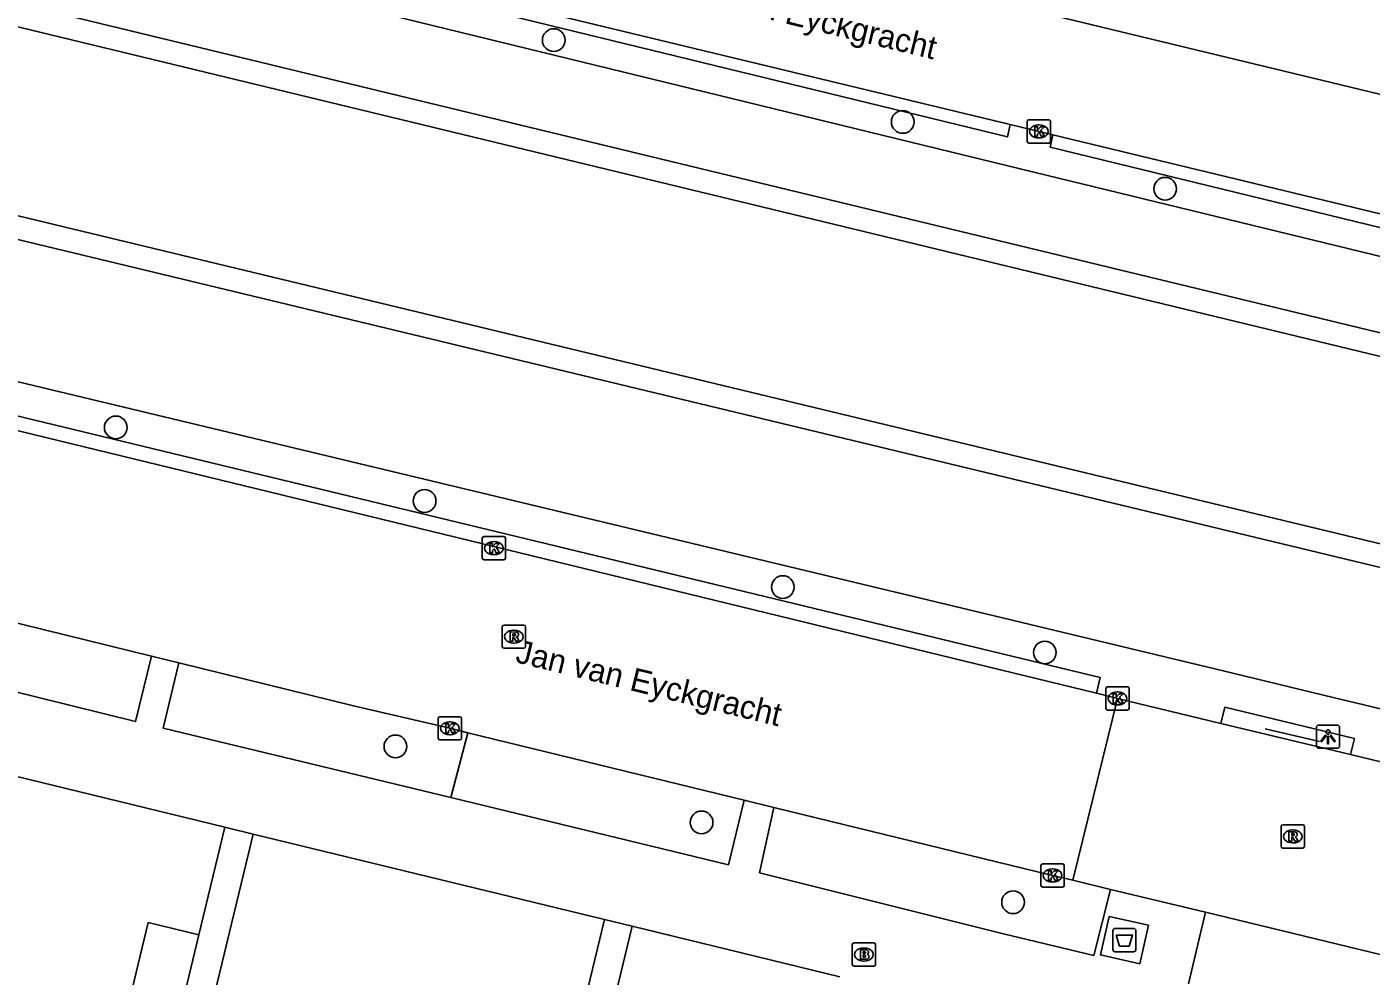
# Model space of a CAD drawing. Extents: x 162812 to 163818, y 381639 to 382470.
# Drawn here: x 163237.4 to 163295.2, y 382298.5 to 382339.3 of the extents above; entities that cross this region are included whole.
import ezdxf

# ---------------------------------------------------------------- set-up
doc = ezdxf.new("R2010")
doc.units = 0
for name, color, linetype in [('IMGEO_Afval_apart_plaats', 7, 'Continuous'), ('IMGEO_Boom', 7, 'Continuous'), ('IMGEO_Brandkraan', 7, 'Continuous'), ('IMGEO_Groenvoorziening', 7, 'Continuous'), ('IMGEO_Haag', 7, 'Continuous'), ('IMGEO_Hek', 7, 'Continuous'), ('IMGEO_Kolk', 7, 'Continuous'), ('IMGEO_Lichtpunt', 7, 'Continuous'), ('IMGEO_Openbare_ruimte_label', 7, 'Continuous'), ('IMGEO_Pand', 7, 'Continuous'), ('IMGEO_Rijbaan_lokaal_gesloten', 7, 'Continuous'), ('IMGEO_Rijbaan_lokaal_open', 7, 'Continuous'), ('IMGEO_Rioolput', 7, 'Continuous'), ('IMGEO_Voetpad_gesloten', 7, 'Continuous'), ('IMGEO_Voetpad_open', 7, 'Continuous'), ('IMGEO_Waterloop', 7, 'Continuous')]:
    doc.layers.add(name, color=color, linetype=linetype)

msp = doc.modelspace()

# ---------------------------------------------------------------- linework, layer by layer
at = {"layer": 'IMGEO_Afval_apart_plaats'}
for p, q in [((163284.062, 382299.617), (163284.062, 382300.417)), ((163284.062, 382300.417), (163284.062, 382299.617)), ((163284.162, 382300.517), (163284.952, 382300.517)), ((163284.952, 382300.517), (163284.162, 382300.517)), ((163285.052, 382300.417), (163285.052, 382299.617)), ((163285.052, 382299.617), (163285.052, 382300.417)), ((163284.952, 382299.517), (163284.162, 382299.517)), ((163284.162, 382299.517), (163284.952, 382299.517))]:
    msp.add_line(p, q, dxfattribs=at)
msp.add_lwpolyline([(163284.205, 382300.231), (163284.909, 382300.231), (163284.76, 382299.761), (163284.354, 382299.761), (163284.205, 382300.231)], dxfattribs=at)
for centre, start, end in [((163284.162, 382300.417), 90, 180), ((163284.162, 382300.417), 90, 180), ((163284.952, 382300.417), 0, 90), ((163284.952, 382300.417), 360, 90), ((163284.162, 382299.617), 180, 270), ((163284.162, 382299.617), 180, 270), ((163284.952, 382299.617), 270, 0), ((163284.952, 382299.617), 270, 0)]:
    msp.add_arc(centre, 0.1, start, end, dxfattribs=at)
at = {"layer": 'IMGEO_Boom'}
for centre in [(163260.028, 382338.71), (163275.029, 382335.193), (163286.311, 382332.321), (163241.202, 382322.057), (163254.477, 382318.896), (163269.876, 382315.194), (163281.138, 382312.38), (163253.224, 382308.342), (163266.381, 382305.075), (163279.772, 382301.645)]:
    msp.add_circle(centre, 0.489, dxfattribs=at)
at = {"layer": 'IMGEO_Brandkraan'}
for p, q in [((163272.861, 382298.969), (163272.861, 382299.821)), ((163272.936, 382299.895), (163273.788, 382299.895)), ((163273.862, 382299.821), (163273.862, 382298.969)), ((163273.372, 382299.115), (163273.347, 382299.115)), ((163273.349, 382299.675), (163273.374, 382299.675)), ((163273.788, 382298.895), (163272.936, 382298.895))]:
    msp.add_line(p, q, dxfattribs=at)
for points in [[(163272.861, 382298.969), (163272.861, 382299.821)], [(163272.936, 382299.895), (163273.788, 382299.895)], [(163273.862, 382299.821), (163273.862, 382298.969)], [(163273.209, 382299.595), (163273.209, 382299.195), (163273.422, 382299.195)], [(163273.44, 382299.595), (163273.209, 382299.595)], [(163273.388, 382299.514), (163273.334, 382299.514), (163273.334, 382299.438)], [(163273.334, 382299.438), (163273.387, 382299.438)], [(163273.396, 382299.362), (163273.334, 382299.362), (163273.334, 382299.281)], [(163273.334, 382299.281), (163273.396, 382299.281)], [(163273.788, 382298.895), (163272.936, 382298.895)]]:
    msp.add_lwpolyline(points, dxfattribs=at)
for centre, radius, start, end in [((163272.938, 382299.819), 0.0765, 91.55205, 178.44795), ((163272.938, 382299.819), 0.0765, 91.55205, 178.44795), ((163273.786, 382299.819), 0.0765, 1.55205, 88.44795), ((163273.786, 382299.819), 0.0765, 1.55205, 88.44795), ((163273.389, 382299.476), 0.0379, 267.82845, 90.93552), ((163273.397, 382299.321), 0.0404, 269.87594, 90.50774), ((163273.428, 382299.446), 0.251, 268.66757, 293.53466), ((163273.444, 382299.45), 0.145, 59.4692, 91.53667), ((163273.469, 382299.497), 0.0922, 285.51372, 58.15012), ((163273.474, 382299.305), 0.105, 301.31148, 78.98903), ((163272.938, 382298.971), 0.0765, 181.55205, 268.44795), ((163272.938, 382298.971), 0.0765, 181.55205, 268.44795), ((163273.786, 382298.971), 0.0765, 271.55205, 358.44795), ((163273.786, 382298.971), 0.0765, 271.55205, 358.44795)]:
    msp.add_arc(centre, radius, start, end, dxfattribs=at)
for centre, major_axis, ratio, start_param, end_param in [((163273.348, 382299.395), (-0.387, 0.002), 0.722429, 4.712389, 7.853982), ((163273.373, 382299.395), (-0.39, 0.002), 0.717154, 1.570796, 4.712389)]:
    msp.add_ellipse(centre, major_axis=major_axis, ratio=ratio, start_param=start_param, end_param=end_param, dxfattribs=at)
at = {"layer": 'IMGEO_Groenvoorziening'}
for points in [[(163124.212, 382361.733), (163124.199, 382361.634), (163124.179, 382361.483), (163124.214, 382360.617), (163124.398, 382359.77), (163124.726, 382358.967), (163125.186, 382358.233), (163125.766, 382357.589), (163126.448, 382357.055), (163127.212, 382356.646), (163128.031, 382356.38), (163312.533, 382311.945)], [(163311.162, 382306.237), (163301.48, 382308.531), (163294.794, 382310.149), (163293.59, 382310.438), (163289.215, 382311.492), (163276.806, 382314.466), (163227.546, 382326.288), (163216.745, 382328.88), (163173.674, 382339.217), (163145.028, 382346.093), (163120.818, 382351.903)], [(163219.616, 382347.944), (163281.197, 382332.909), (163315.558, 382324.549)], [(163314.82, 382321.474), (163218.158, 382344.843)], [(163256.335, 382308.933), (163255.599, 382306.14)]]:
    msp.add_lwpolyline(points, dxfattribs=at)
at = {"layer": 'IMGEO_Haag'}
for points in [[(163257.21, 382340.506), (163257.104, 382340.006), (163279.529, 382334.55), (163279.654, 382335.08)], [(163281.483, 382334.638), (163281.37, 382334.102), (163304.184, 382328.551), (163304.335, 382329.113)], [(163232.883, 382322.92), (163233.029, 382323.496), (163283.516, 382311.307), (163283.353, 382310.627)], [(163288.699, 382309.335), (163288.871, 382310.025), (163294.448, 382308.678), (163294.281, 382307.988)]]:
    msp.add_lwpolyline(points, dxfattribs=at)
at = {"layer": 'IMGEO_Hek'}
msp.add_lwpolyline([(163290.608, 382309.097), (163292.944, 382308.555)], dxfattribs=at)
at = {"layer": 'IMGEO_Kolk'}
for p, q in [((163280.381, 382334.358), (163280.381, 382335.21)), ((163280.456, 382335.284), (163281.308, 382335.284)), ((163280.869, 382335.064), (163280.894, 382335.064)), ((163281.382, 382335.21), (163281.382, 382334.358)), ((163280.892, 382334.504), (163280.867, 382334.504)), ((163281.308, 382334.284), (163280.456, 382334.284)), ((163256.956, 382316.442), (163256.956, 382317.294)), ((163257.031, 382317.368), (163257.883, 382317.368)), ((163257.444, 382317.148), (163257.469, 382317.148)), ((163257.957, 382317.294), (163257.957, 382316.442)), ((163257.467, 382316.588), (163257.442, 382316.588)), ((163257.883, 382316.368), (163257.031, 382316.368)), ((163283.76, 382309.98), (163283.76, 382310.832)), ((163283.835, 382310.906), (163284.687, 382310.906)), ((163284.248, 382310.686), (163284.273, 382310.686)), ((163284.761, 382310.832), (163284.761, 382309.98)), ((163284.271, 382310.126), (163284.246, 382310.126)), ((163255.063, 382308.694), (163255.063, 382309.546)), ((163255.138, 382309.62), (163255.99, 382309.62)), ((163256.064, 382309.546), (163256.064, 382308.694)), ((163284.687, 382309.906), (163283.835, 382309.906)), ((163255.551, 382309.4), (163255.576, 382309.4)), ((163255.99, 382308.62), (163255.138, 382308.62)), ((163255.574, 382308.84), (163255.549, 382308.84)), ((163280.97, 382302.368), (163280.97, 382303.22)), ((163281.045, 382303.294), (163281.897, 382303.294)), ((163281.971, 382303.22), (163281.971, 382302.368)), ((163281.458, 382303.074), (163281.483, 382303.074)), ((163281.897, 382302.294), (163281.045, 382302.294)), ((163281.481, 382302.514), (163281.456, 382302.514))]:
    msp.add_line(p, q, dxfattribs=at)
for points in [[(163280.381, 382334.358), (163280.381, 382335.21)], [(163280.456, 382335.284), (163281.308, 382335.284)], [(163280.702, 382334.984), (163280.825, 382334.984), (163280.825, 382334.833), (163280.955, 382334.984), (163281.119, 382334.984), (163280.973, 382334.833), (163281.126, 382334.584), (163280.974, 382334.584), (163280.889, 382334.748), (163280.825, 382334.681), (163280.825, 382334.584), (163280.702, 382334.584), (163280.702, 382334.984)], [(163281.382, 382335.21), (163281.382, 382334.358)], [(163281.308, 382334.284), (163280.456, 382334.284)], [(163256.956, 382316.442), (163256.956, 382317.294)], [(163257.031, 382317.368), (163257.883, 382317.368)], [(163257.277, 382317.068), (163257.4, 382317.068), (163257.4, 382316.917), (163257.53, 382317.068), (163257.694, 382317.068), (163257.548, 382316.917), (163257.701, 382316.668), (163257.549, 382316.668), (163257.464, 382316.832), (163257.4, 382316.765), (163257.4, 382316.668), (163257.277, 382316.668), (163257.277, 382317.068)], [(163257.957, 382317.294), (163257.957, 382316.442)], [(163257.883, 382316.368), (163257.031, 382316.368)], [(163283.76, 382309.98), (163283.76, 382310.832)], [(163283.835, 382310.906), (163284.687, 382310.906)], [(163284.761, 382310.832), (163284.761, 382309.98)], [(163284.081, 382310.606), (163284.204, 382310.606), (163284.204, 382310.455), (163284.334, 382310.606), (163284.498, 382310.606), (163284.352, 382310.455), (163284.505, 382310.206), (163284.353, 382310.206), (163284.268, 382310.37), (163284.204, 382310.303), (163284.204, 382310.206), (163284.081, 382310.206), (163284.081, 382310.606)], [(163255.063, 382308.694), (163255.063, 382309.546)], [(163255.138, 382309.62), (163255.99, 382309.62)], [(163256.064, 382309.546), (163256.064, 382308.694)], [(163284.687, 382309.906), (163283.835, 382309.906)], [(163255.384, 382309.32), (163255.507, 382309.32), (163255.507, 382309.169), (163255.637, 382309.32), (163255.801, 382309.32), (163255.655, 382309.169), (163255.808, 382308.92), (163255.656, 382308.92), (163255.571, 382309.084), (163255.507, 382309.017), (163255.507, 382308.92), (163255.384, 382308.92), (163255.384, 382309.32)], [(163255.99, 382308.62), (163255.138, 382308.62)], [(163280.97, 382302.368), (163280.97, 382303.22)], [(163281.045, 382303.294), (163281.897, 382303.294)], [(163281.971, 382303.22), (163281.971, 382302.368)], [(163281.291, 382302.994), (163281.414, 382302.994), (163281.414, 382302.843), (163281.544, 382302.994), (163281.708, 382302.994), (163281.562, 382302.843), (163281.715, 382302.594), (163281.563, 382302.594), (163281.478, 382302.758), (163281.414, 382302.691), (163281.414, 382302.594), (163281.291, 382302.594), (163281.291, 382302.994)], [(163281.897, 382302.294), (163281.045, 382302.294)]]:
    msp.add_lwpolyline(points, dxfattribs=at)
for centre, start, end in [((163280.458, 382335.208), 91.55205, 178.44795), ((163280.458, 382335.208), 91.55205, 178.44795), ((163281.306, 382335.208), 1.55205, 88.44795), ((163281.306, 382335.208), 1.55205, 88.44795), ((163280.458, 382334.36), 181.55205, 268.44795), ((163280.458, 382334.36), 181.55205, 268.44795), ((163281.306, 382334.36), 271.55205, 358.44795), ((163281.306, 382334.36), 271.55205, 358.44795), ((163257.033, 382317.292), 91.55205, 178.44795), ((163257.033, 382317.292), 91.55205, 178.44795), ((163257.881, 382317.292), 1.55205, 88.44795), ((163257.881, 382317.292), 1.55205, 88.44795), ((163257.033, 382316.444), 181.55205, 268.44795), ((163257.033, 382316.444), 181.55205, 268.44795), ((163257.881, 382316.444), 271.55205, 358.44795), ((163257.881, 382316.444), 271.55205, 358.44795), ((163283.837, 382310.83), 91.55205, 178.44795), ((163283.837, 382310.83), 91.55205, 178.44795), ((163284.685, 382310.83), 1.55205, 88.44795), ((163284.685, 382310.83), 1.55205, 88.44795), ((163255.14, 382309.544), 91.55205, 178.44795), ((163255.14, 382309.544), 91.55205, 178.44795), ((163255.988, 382309.544), 1.55205, 88.44795), ((163255.988, 382309.544), 1.55205, 88.44795), ((163283.837, 382309.982), 181.55205, 268.44795), ((163283.837, 382309.982), 181.55205, 268.44795), ((163284.685, 382309.982), 271.55205, 358.44795), ((163284.685, 382309.982), 271.55205, 358.44795), ((163255.14, 382308.696), 181.55205, 268.44795), ((163255.14, 382308.696), 181.55205, 268.44795), ((163255.988, 382308.696), 271.55205, 358.44795), ((163255.988, 382308.696), 271.55205, 358.44795), ((163281.047, 382303.218), 91.55205, 178.44795), ((163281.047, 382303.218), 91.55205, 178.44795), ((163281.895, 382303.218), 1.55205, 88.44795), ((163281.895, 382303.218), 1.55205, 88.44795), ((163281.047, 382302.37), 181.55205, 268.44795), ((163281.047, 382302.37), 181.55205, 268.44795), ((163281.895, 382302.37), 271.55205, 358.44795), ((163281.895, 382302.37), 271.55205, 358.44795)]:
    msp.add_arc(centre, 0.0765, start, end, dxfattribs=at)
for centre, major_axis, ratio, start_param, end_param in [((163280.868, 382334.784), (-0.387, 0.002), 0.722429, 4.712389, 7.853982), ((163280.893, 382334.784), (-0.39, 0.002), 0.717154, 1.570796, 4.712389), ((163257.443, 382316.868), (-0.387, 0.002), 0.722429, 4.712389, 7.853982), ((163257.468, 382316.868), (-0.39, 0.002), 0.717154, 1.570796, 4.712389), ((163284.247, 382310.406), (-0.387, 0.002), 0.722429, 4.712389, 7.853982), ((163284.272, 382310.406), (-0.39, 0.002), 0.717154, 1.570796, 4.712389), ((163255.55, 382309.12), (-0.387, 0.002), 0.722429, 4.712389, 7.853982), ((163255.575, 382309.12), (-0.39, 0.002), 0.717154, 1.570796, 4.712389), ((163281.457, 382302.794), (-0.387, 0.002), 0.722429, 4.712389, 7.853982), ((163281.482, 382302.794), (-0.39, 0.002), 0.717154, 1.570796, 4.712389)]:
    msp.add_ellipse(centre, major_axis=major_axis, ratio=ratio, start_param=start_param, end_param=end_param, dxfattribs=at)
at = {"layer": 'IMGEO_Lichtpunt'}
for p, q in [((163292.812, 382309.164), (163292.812, 382308.357)), ((163292.812, 382309.164), (163292.812, 382308.357)), ((163293.714, 382309.259), (163292.906, 382309.259)), ((163293.714, 382309.259), (163292.906, 382309.259)), ((163293.808, 382308.357), (163293.808, 382309.164)), ((163293.808, 382308.357), (163293.808, 382309.164)), ((163292.906, 382308.263), (163293.714, 382308.263)), ((163292.906, 382308.263), (163293.714, 382308.263))]:
    msp.add_line(p, q, dxfattribs=at)
for points in [[(163293.186, 382308.828), (163293.225, 382308.8), (163293.037, 382308.538), (163292.999, 382308.565), (163293.186, 382308.828)], [(163293.288, 382308.78), (163293.335, 382308.78), (163293.335, 382308.458), (163293.288, 382308.458), (163293.288, 382308.78)], [(163293.398, 382308.8), (163293.436, 382308.827), (163293.623, 382308.565), (163293.584, 382308.537), (163293.398, 382308.8)]]:
    msp.add_lwpolyline(points, dxfattribs=at)
msp.add_circle((163293.311, 382308.962), 0.0994, dxfattribs=at)
for centre, start, end in [((163292.906, 382309.164), 90, 180), ((163292.906, 382309.164), 90, 180), ((163293.714, 382309.164), 0, 90), ((163293.714, 382309.164), 0, 90), ((163292.906, 382308.357), 180, 270), ((163292.906, 382308.357), 180, 270), ((163293.714, 382308.357), 270, 0), ((163293.714, 382308.357), 270, 360)]:
    msp.add_arc(centre, 0.0946, start, end, dxfattribs=at)
at = {"layer": 'IMGEO_Pand'}
for points in [[(163244.773, 382300.239), (163242.596, 382300.765), (163241.113, 382294.621), (163243.29, 382294.095)], [(163244.773, 382300.239), (163243.29, 382294.095)]]:
    msp.add_lwpolyline(points, dxfattribs=at)
at = {"layer": 'IMGEO_Rijbaan_lokaal_gesloten'}
for points in [[(163283.353, 382310.627), (163273.036, 382313.145), (163257.456, 382316.932), (163253.691, 382317.85), (163232.883, 382322.92)], [(163230.608, 382315.208), (163242.735, 382312.225)], [(163243.916, 382311.934), (163242.735, 382312.225)], [(163256.335, 382308.933), (163255.565, 382309.121), (163251.415, 382310.083), (163243.916, 382311.934)], [(163284.261, 382310.405), (163283.353, 382310.627)], [(163268.21, 382306.033), (163256.335, 382308.933)], [(163269.487, 382305.721), (163268.21, 382306.033)], [(163269.487, 382305.721), (163281.471, 382302.795), (163282.348, 382302.586)]]:
    msp.add_lwpolyline(points, dxfattribs=at)
at = {"layer": 'IMGEO_Rijbaan_lokaal_open'}
for points in [[(163306.632, 382333.703), (163233.817, 382351.293)], [(163257.21, 382340.506), (163279.654, 382335.08)], [(163279.654, 382335.08), (163281.483, 382334.638)], [(163304.335, 382329.113), (163281.483, 382334.638)], [(163282.348, 382302.586), (163284.261, 382310.405)], [(163288.699, 382309.335), (163284.261, 382310.405)], [(163294.281, 382307.988), (163288.699, 382309.335)], [(163300.251, 382306.548), (163294.281, 382307.988)], [(163282.348, 382302.586), (163283.964, 382302.196)], [(163288.041, 382301.212), (163283.964, 382302.196)], [(163298.385, 382298.714), (163288.041, 382301.212)]]:
    msp.add_lwpolyline(points, dxfattribs=at)
at = {"layer": 'IMGEO_Rioolput'}
for p, q in [((163257.89, 382313.562), (163258.742, 382313.562)), ((163257.815, 382312.636), (163257.815, 382313.488)), ((163258.303, 382313.342), (163258.328, 382313.342)), ((163258.816, 382313.488), (163258.816, 382312.636)), ((163258.742, 382312.562), (163257.89, 382312.562)), ((163258.326, 382312.782), (163258.301, 382312.782)), ((163291.295, 382304.048), (163291.295, 382304.9)), ((163291.37, 382304.974), (163292.222, 382304.974)), ((163292.296, 382304.9), (163292.296, 382304.048)), ((163291.783, 382304.754), (163291.808, 382304.754)), ((163292.222, 382303.974), (163291.37, 382303.974)), ((163291.806, 382304.194), (163291.781, 382304.194))]:
    msp.add_line(p, q, dxfattribs=at)
for points in [[(163257.89, 382313.562), (163258.742, 382313.562)], [(163257.815, 382312.636), (163257.815, 382313.488)], [(163258.404, 382313.26), (163258.152, 382313.262), (163258.152, 382312.862)], [(163258.152, 382312.862), (163258.276, 382312.862), (163258.276, 382313.024), (163258.287, 382313.024)], [(163258.33, 382313.181), (163258.276, 382313.181), (163258.276, 382313.1)], [(163258.276, 382313.1), (163258.328, 382313.1)], [(163258.334, 382312.995), (163258.405, 382312.862), (163258.545, 382312.862), (163258.48, 382312.988)], [(163258.816, 382313.488), (163258.816, 382312.636)], [(163258.742, 382312.562), (163257.89, 382312.562)], [(163291.295, 382304.048), (163291.295, 382304.9)], [(163291.37, 382304.974), (163292.222, 382304.974)], [(163292.296, 382304.9), (163292.296, 382304.048)], [(163291.884, 382304.672), (163291.632, 382304.674), (163291.632, 382304.274)], [(163291.632, 382304.274), (163291.756, 382304.274), (163291.756, 382304.436), (163291.767, 382304.436)], [(163291.81, 382304.593), (163291.756, 382304.593), (163291.756, 382304.512)], [(163291.756, 382304.512), (163291.808, 382304.512)], [(163291.814, 382304.407), (163291.885, 382304.274), (163292.025, 382304.274), (163291.96, 382304.4)], [(163292.222, 382303.974), (163291.37, 382303.974)]]:
    msp.add_lwpolyline(points, dxfattribs=at)
for centre, radius, start, end in [((163257.892, 382313.486), 0.0765, 91.55205, 178.44795), ((163257.892, 382313.486), 0.0765, 91.55205, 178.44795), ((163258.74, 382313.486), 0.0765, 1.55205, 88.44795), ((163258.74, 382313.486), 0.0765, 1.55205, 88.44795), ((163258.286, 382312.971), 0.0533, 26.02933, 88.69889), ((163258.312, 382313.289), 0.19, 274.7715, 282.96867), ((163258.336, 382313.085), 0.0964, 77.00612, 93.18647), ((163258.35, 382313.142), 0.0378, 276.66336, 79.67722), ((163258.403, 382313.15), 0.109, 350.36119, 89.41601), ((163258.401, 382313.15), 0.112, 277.58423, 350.98172), ((163258.385, 382312.935), 0.108, 29.51342, 73.79051), ((163257.892, 382312.638), 0.0765, 181.55205, 268.44795), ((163257.892, 382312.638), 0.0765, 181.55205, 268.44795), ((163258.74, 382312.638), 0.0765, 271.55205, 358.44795), ((163258.74, 382312.638), 0.0765, 271.55205, 358.44795), ((163291.372, 382304.898), 0.0765, 91.55205, 178.44795), ((163291.372, 382304.898), 0.0765, 91.55205, 178.44795), ((163292.22, 382304.898), 0.0765, 1.55205, 88.44795), ((163292.22, 382304.898), 0.0765, 1.55205, 88.44795), ((163291.766, 382304.383), 0.0533, 26.02933, 88.69889), ((163291.792, 382304.701), 0.19, 274.7715, 282.96867), ((163291.816, 382304.497), 0.0964, 77.00612, 93.18647), ((163291.83, 382304.554), 0.0378, 276.66336, 79.67722), ((163291.883, 382304.562), 0.109, 350.36119, 89.41601), ((163291.881, 382304.562), 0.112, 277.58423, 350.98172), ((163291.865, 382304.347), 0.108, 29.51342, 73.79051), ((163291.372, 382304.05), 0.0765, 181.55205, 268.44795), ((163291.372, 382304.05), 0.0765, 181.55205, 268.44795), ((163292.22, 382304.05), 0.0765, 271.55205, 358.44795), ((163292.22, 382304.05), 0.0765, 271.55205, 358.44795)]:
    msp.add_arc(centre, radius, start, end, dxfattribs=at)
for centre, major_axis, ratio, start_param, end_param in [((163258.302, 382313.062), (-0.387, 0.002), 0.722429, 4.712389, 7.853982), ((163258.327, 382313.062), (-0.39, 0.002), 0.717154, 1.570796, 4.712389), ((163291.782, 382304.474), (-0.387, 0.002), 0.722429, 4.712389, 7.853982), ((163291.807, 382304.474), (-0.39, 0.002), 0.717154, 1.570796, 4.712389)]:
    msp.add_ellipse(centre, major_axis=major_axis, ratio=ratio, start_param=start_param, end_param=end_param, dxfattribs=at)
at = {"layer": 'IMGEO_Voetpad_gesloten'}
msp.add_lwpolyline([(163283.898, 382301.032), (163285.587, 382300.654), (163285.217, 382299.001), (163283.528, 382299.379), (163283.898, 382301.032)], dxfattribs=at)
at = {"layer": 'IMGEO_Voetpad_open'}
for points in [[(163242.735, 382312.225), (163242.042, 382309.407), (163229.875, 382312.418), (163230.608, 382315.208)], [(163243.916, 382311.934), (163243.238, 382309.129), (163255.599, 382306.14)], [(163236.827, 382307.077), (163245.892, 382304.87)], [(163255.599, 382306.14), (163267.536, 382303.253), (163268.21, 382306.033)], [(163283.964, 382302.196), (163283.239, 382299.353), (163279.364, 382300.278), (163268.873, 382302.914), (163269.487, 382305.721)], [(163262.216, 382300.897), (163253.055, 382262.982), (163237.933, 382266.607), (163247.107, 382304.575)], [(163245.892, 382304.87), (163244.773, 382300.239)], [(163245.892, 382304.87), (163247.107, 382304.575)], [(163247.107, 382304.575), (163262.216, 382300.897)], [(163262.216, 382300.897), (163263.401, 382300.608)], [(163287.315, 382298.14), (163288.041, 382301.212)], [(163262.297, 382296.038), (163263.401, 382300.608)], [(163263.401, 382300.608), (163272.32, 382298.437)]]:
    msp.add_lwpolyline(points, dxfattribs=at)
at = {"layer": 'IMGEO_Waterloop'}
for points in [[(163312.766, 382312.917), (163128.265, 382357.352)], [(163217.922, 382343.9), (163218.023, 382343.875), (163314.587, 382320.502)]]:
    msp.add_lwpolyline(points, dxfattribs=at)

# ---------------------------------------------------------------- texts
at = {"layer": 'IMGEO_Openbare_ruimte_label'}
for rotation, p in [(346.29711, (163265.005, 382340.64)), (346.28353, (163258.337, 382311.971))]:
    msp.add_text('Jan van Eyckgracht', height=1, rotation=rotation, dxfattribs=at).set_placement(p)

doc.saveas('drawing.dxf')
